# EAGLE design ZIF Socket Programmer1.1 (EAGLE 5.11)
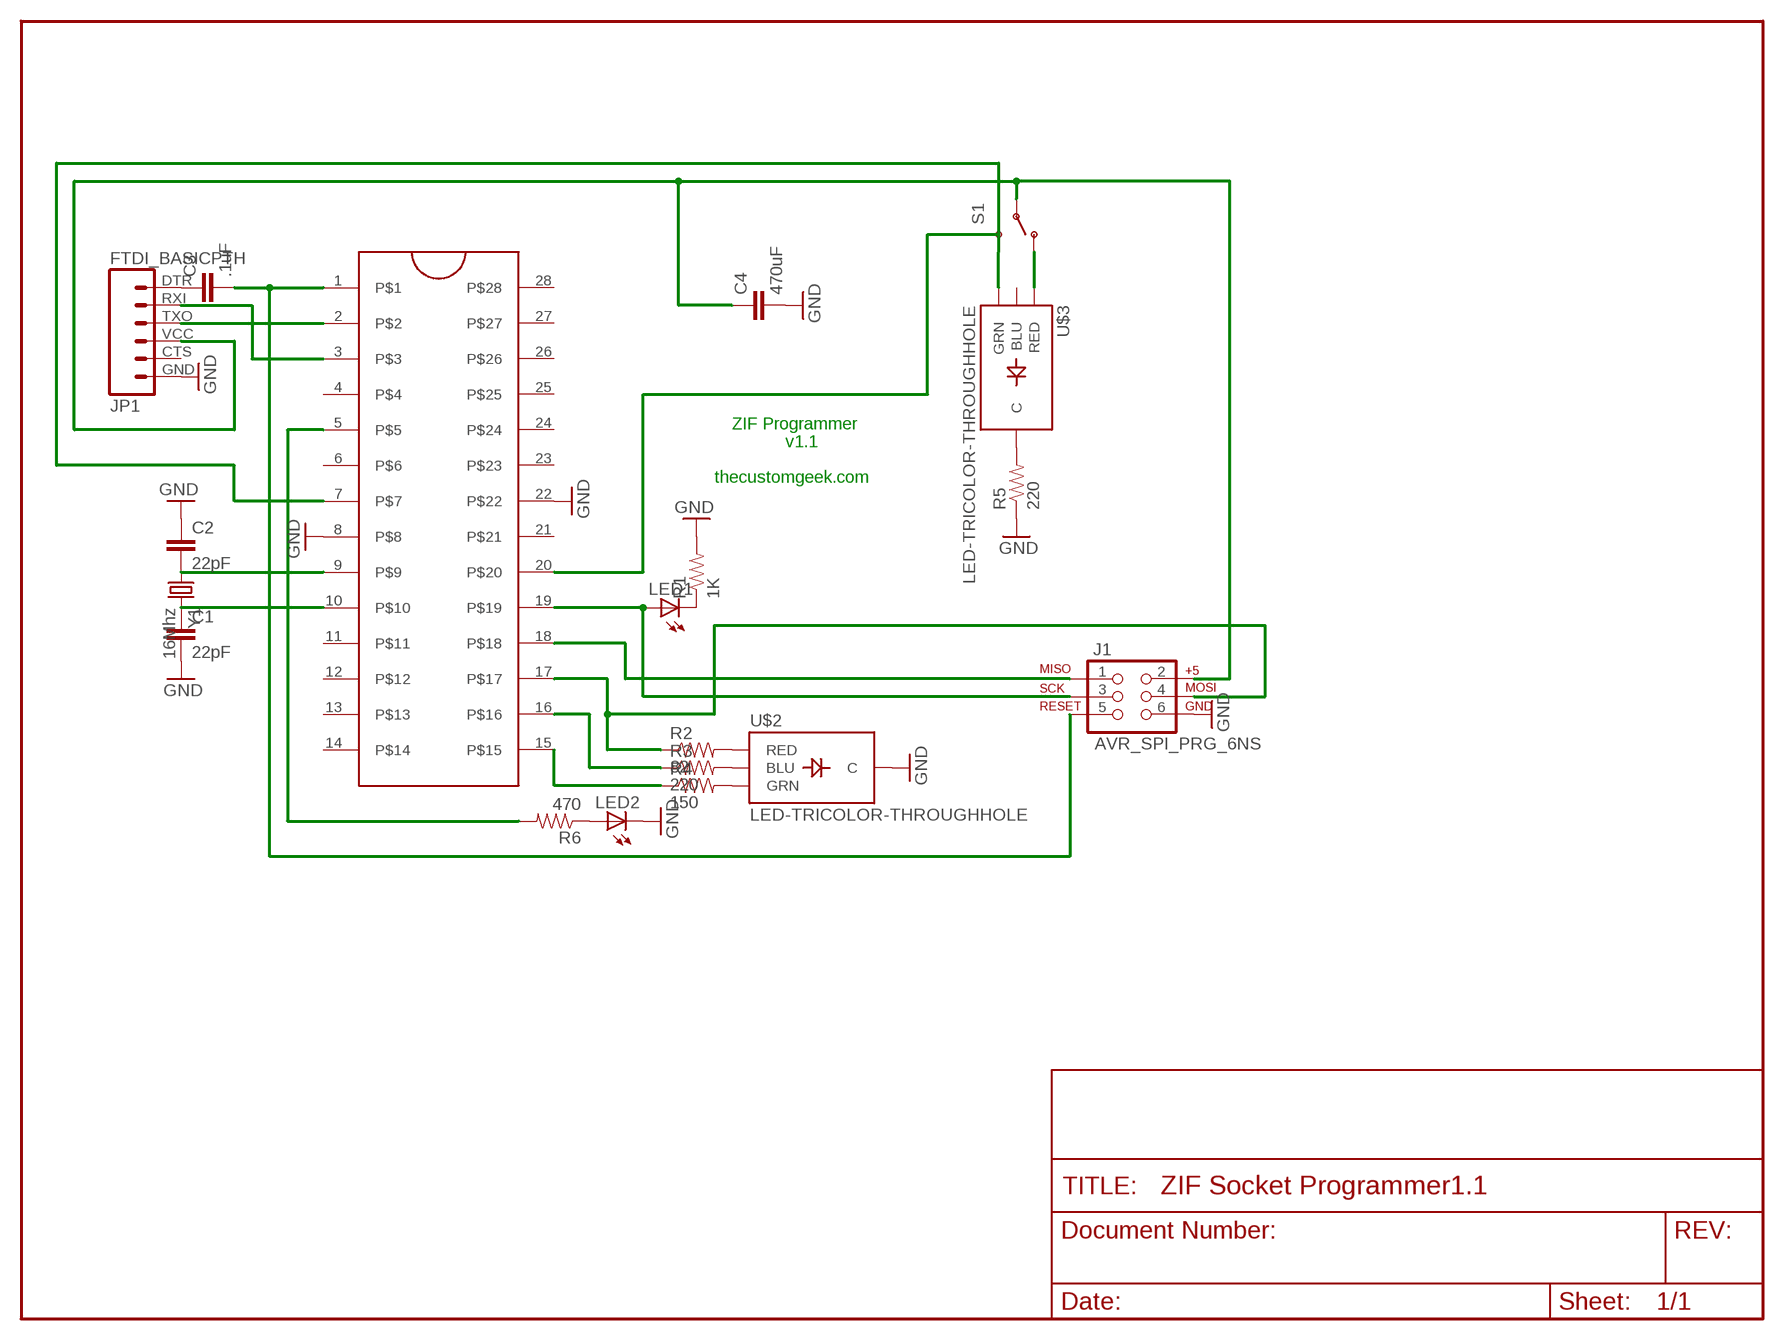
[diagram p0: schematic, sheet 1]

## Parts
C1  22pF  CAPKIT  [CAP-PTH-SMALL-KIT]
C2  22pF  CAPKIT  [CAP-PTH-SMALL-KIT]
C3  .1uF  CAPKIT  [CAP-PTH-SMALL-KIT]
C4  470uF  CAPPTH3  [CAP-PTH-LARGE]
J1  AVR_SPI_PRG_6NS  [2X3-NS]
JP1  FTDI_BASICPTH  [FTDI_BASIC]
LED1  LED3MM  [LED3MM]
LED2  LED3MM  [LED3MM]
R1  1K  RESISTORPTH-1/4W  [AXIAL-0.4]
R2  82  RESISTORPTH-1/4W  [AXIAL-0.4]
R3  220  RESISTORPTH-1/4W  [AXIAL-0.4]
R4  150  RESISTORPTH-1/4W  [AXIAL-0.4]
R5  220  RESISTORPTH-1/4W  [AXIAL-0.4]
R6  470  RESISTORPTH-1/4W  [AXIAL-0.4]
S1  SWITCH-SPSTSMD2  [SWITCH-SPDT-SMD]
U$1  ZIFSOCKET-28-3ZIFFSOCKET-28-3  [DIL28-3-ZIF_SOCKET]
U$2  LED-TRICOLOR-THROUGHHOLE  [LED-TRICOLOR-THROUGHHOLE]
U$3  LED-TRICOLOR-THROUGHHOLE  [LED-TRICOLOR-THROUGHHOLE]
Y1  16Mhz  CRYSTALHC49US  [HC49US]

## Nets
GND: C1.2 C2.1 C4.2 J1.6 JP1.GND LED2.K(C) R1.P$2 R5.P$1 U$1.8 U$1.22 U$2.GND(C)
N$1: J1.1 U$1.18
N$2: J1.3 LED1.A U$1.19
N$3: C3.2 J1.5 U$1.1
N$4: C3.1 JP1.DTR
N$5: LED1.K(C) R1.P$1
N$6: R2.P$2 U$2.RED
N$7: R3.P$2 U$2.BLU
N$8: R4.P$2 U$2.GRN
N$9: R5.P$2 U$3.GND(C)
N$10: LED2.A R6.P$1
N$11: C1.1 U$1.10 Y1.2
N$12: C2.2 U$1.9 Y1.1
N$13: JP1.RXI U$1.3
N$14: JP1.TXO U$1.2
N$15: C4.1 J1.2 JP1.VCC S1.2(P)
N$16: J1.4 R2.P$1 U$1.17
N$17: R3.P$1 U$1.16
N$18: R4.P$1 U$1.15
N$20: S1.1(O) U$3.RED
N$21: S1.3(S) U$1.7 U$1.20 U$3.GRN
N$23: R6.P$2 U$1.5
Unconnected: JP1.CTS U$1.4 U$1.6 U$1.11 U$1.12 U$1.13 U$1.14 U$1.21 U$1.23 U$1.24 U$1.25 U$1.26 U$1.27 U$1.28 U$3.BLU

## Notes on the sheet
- ZIF Programmer
- v1.1
- thecustomgeek.com

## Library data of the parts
C1-C4 = SparkFun:CAP: Capacitor
J1 = SparkFun:AVR_SPI_PRG_6: AVR ISP 6 Pin This is the reduced ISP connector for AVR programming. Common on Arduino. This footprint will take up less PCB space and can be used with a 10-pin to 6-pin adapter such as SKU: BOB-08508
JP1 = SparkFun:FTDI_BASIC: FTDI Basic: 3.3V and 5V
LED1 LED2 = SparkFun:LED: LEDs
R1-R6 = SparkFun:RESISTOR: Resistor
S1 = SparkFun:SWITCH-SPST: SPST Switch Simple slide switch. Spark Fun Electronics SKU : COM-00102
U$1 = SparkFun:ZIFSOCKET-28-3
U$2 U$3 = SparkFun:LED-TRICOLOR-THROUGHHOLE
Y1 = SparkFun:CRYSTAL: Crystals

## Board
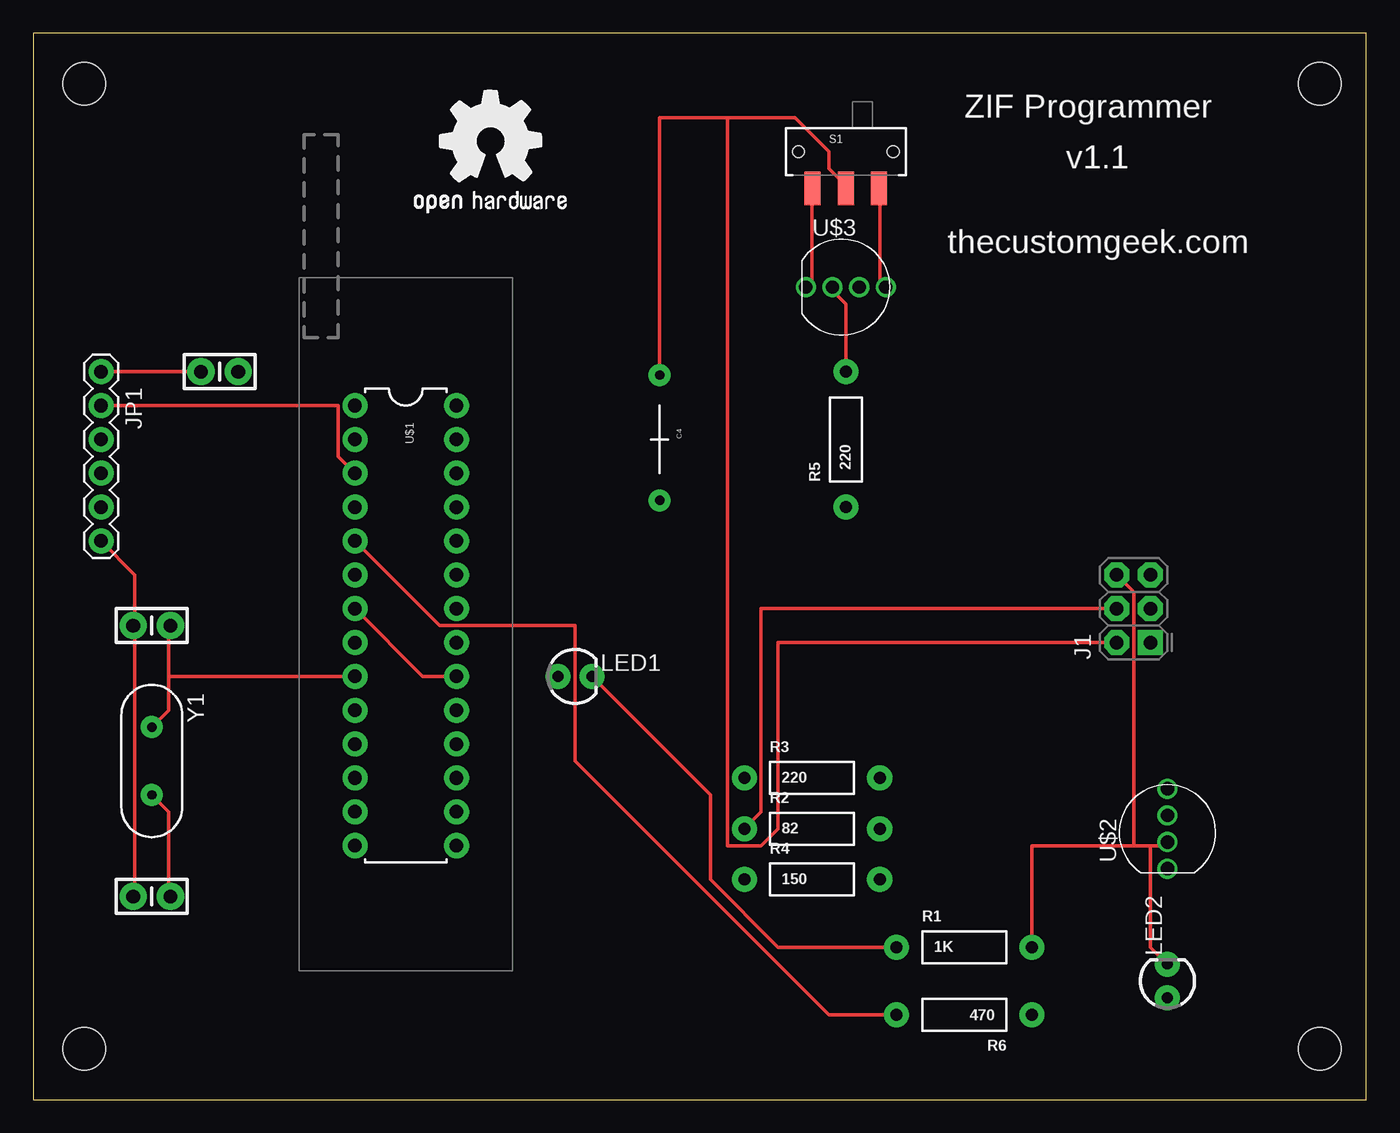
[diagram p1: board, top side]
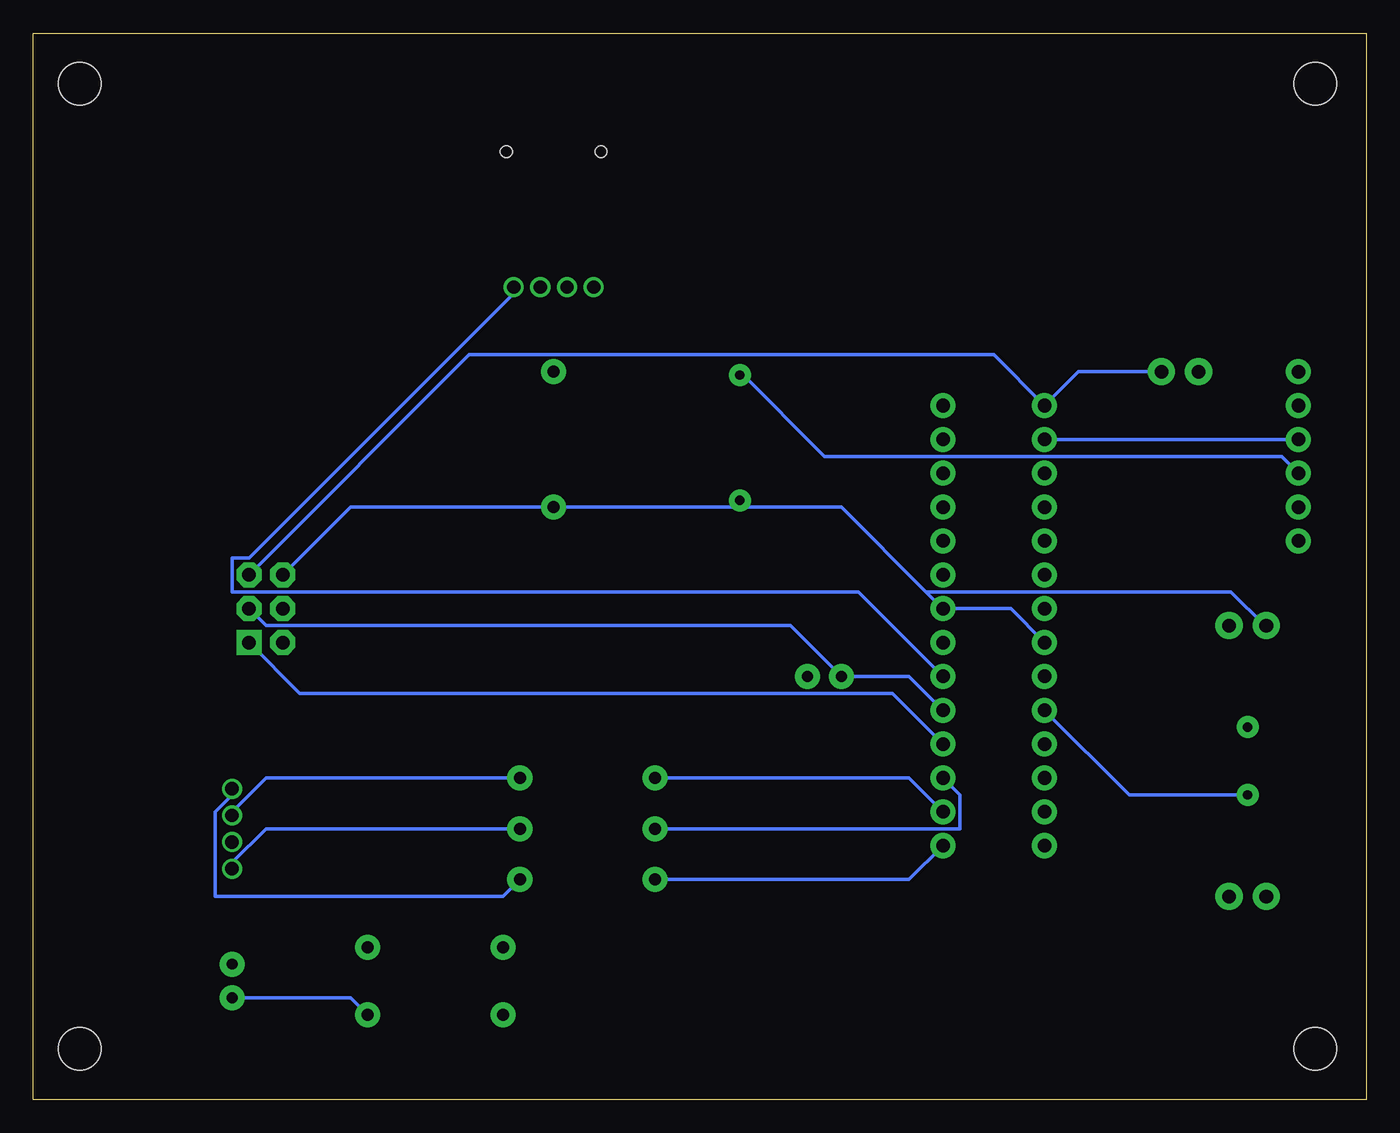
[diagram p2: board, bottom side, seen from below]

Size 100 x 80 mm. Coordinates in mm from the lower left corner, seen from the top.
Outline: 0,0 100,0 100,80 0,80 0,0
Copper layers (1*16): Top 0.035mm / dielectric 1.5mm / Bottom 0.035mm
Design rules "default": minimum track width 10mil, minimum drill 0.6mm, track to track 8mil, track to pad 8mil, pad to pad 8mil, via to via 8mil, smd to smd 8mil, copper to edge 40mil, drill to drill 8mil, minimum pad ring 10mil, minimum via ring 8mil, stop-mask expansion 4mil, vias tented up to drill 0mil, thermal gap 10mil
Holes 3.2 mm at 3.81,76.2 96.52,76.2 96.52,3.81 3.81,3.81

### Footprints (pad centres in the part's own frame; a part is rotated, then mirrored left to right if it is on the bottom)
CAP-PTH-SMALL-KIT = drill 1.016 pad 2.032 round: 1 -1.397,0; 2 1.397,0
CAP-PTH-LARGE = drill 0.7 pad 1.651 round: 1 -4.826,0; 2 4.572,0
2X3-NS = drill 1.016 pad 1.88 square: 1 -2.54,-1.27 | drill 1.016 pad 1.88 octagon: 2 -2.54,1.27; 3 0,-1.27; 4 0,1.27; 5 2.54,-1.27; 6 2.54,1.27
FTDI_BASIC = drill 1.016 pad 1.88 round: CTS 10.16,0; DTR 0,0; GND 12.7,0; RXI 2.54,0; TXO 5.08,0; VCC 7.62,0
LED3MM = drill 0.813 pad 1.88 round: A -1.27,0; K 1.27,0
AXIAL-0.4 = drill 0.9 pad 1.88 round: P$1 -5.08,0; P$2 5.08,0
SWITCH-SPDT-SMD = smd 1.2 x 2.5: 1 -2.5,-2.75; 2 0,-2.75; 3 2.5,-2.75 | hole 0.9: -3.55,0; 3.55,0
DIL28-3-ZIF_SOCKET = drill 1.016 pad 1.88 round: 1 -16.51,-3.81; 2 -13.97,-3.81; 3 -11.43,-3.81; 4 -8.89,-3.81; 5 -6.35,-3.81; 6 -3.81,-3.81; 7 -1.27,-3.81; 8 1.27,-3.81; 9 3.81,-3.81; 10 6.35,-3.81; 11 8.89,-3.81; 12 11.43,-3.81; 13 13.97,-3.81; 14 16.51,-3.81; 15 16.51,3.81; 16 13.97,3.81; 17 11.43,3.81; 18 8.89,3.81; 19 6.35,3.81; 20 3.81,3.81; 21 1.27,3.81; 22 -1.27,3.81; 23 -3.81,3.81; 24 -6.35,3.81; 25 -8.89,3.81; 26 -11.43,3.81; 27 -13.97,3.81; 28 -16.51,3.81
LED-TRICOLOR-THROUGHHOLE = drill 1 round: BLU 1,0; GND -1,0; GRN 3,0; RED -3,0
HC49US = drill 0.7 pad 1.651 round: 1 -2.54,0; 2 2.54,0

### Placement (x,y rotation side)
C1  8.89,15.24 180 top
C2  8.89,35.56 0 top
C3  13.97,54.61 0 top
C4  46.99,49.53 270 top
J1  82.55,36.83 90 top
JP1  5.08,54.61 270 top
LED1  40.64,31.75 0 top
LED2  85.09,8.89 90 top
R1  69.85,11.43 0 top
R2  58.42,20.32 0 top
R3  58.42,24.13 0 top
R4  58.42,16.51 0 top
R5  60.96,49.53 90 top
R6  69.85,6.35 180 top
S1  60.96,71.12 0 top
U$1  27.94,35.56 270 top
U$2  85.09,20.32 90 top
U$3  60.96,60.96 0 top
U$4  [OSHW1]  27.94,64.77 0 top
Y1  8.89,25.4 270 top

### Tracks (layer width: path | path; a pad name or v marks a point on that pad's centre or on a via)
GND
  Top 0.254: 82.55,19.05 74.93,19.05 R1.P$2 | 82.55,19.05 83.82,19.05 | 83.82,19.05 85.09,19.05 U$2.GND | J1.6 82.55,38.1 82.55,19.05 | LED2.K 83.82,11.43 83.82,19.05 | JP1.GND 7.62,39.37 7.62,35.56 | 7.62,35.56 7.62,15.24 C1.2 | 7.62,35.56 C2.1
  Bottom 0.254: U$1.8 26.67,36.83 U$1.22 33.02,38.1 | 46.99,44.45 R5.P$1 76.2,44.45 J1.6 | 33.02,38.1 39.37,44.45 46.99,44.45 | 46.99,44.45 C4.2 | 33.02,38.1 10.16,38.1 7.62,35.56 C2.1
N$1
  Bottom 0.254: U$1.18 35.56,30.48 80.01,30.48 J1.1
N$2
  Bottom 0.254: U$1.19 34.29,31.75 LED1.A 43.18,35.56 82.55,35.56 J1.3
N$3
  Bottom 0.254: 15.24,54.61 C3.2 21.59,54.61 U$1.1 27.94,55.88 67.31,55.88 J1.5
N$4
  Top 0.254: JP1.DTR C3.1 12.7,54.61
N$5
  Top 0.254: LED1.K 50.8,22.86 50.8,16.51 55.88,11.43 R1.P$1
N$6
  Bottom 0.254: R2.P$2 82.55,20.32 85.09,17.78 U$2.RED
N$7
  Bottom 0.254: R3.P$2 82.55,24.13 85.09,21.59 U$2.BLU
N$8
  Bottom 0.254: R4.P$2 64.77,15.24 86.36,15.24 86.36,21.59 85.09,22.86 U$2.GRN
N$9
  Top 0.254: R5.P$2 60.96,59.69 59.69,60.96 U$3.GND
N$10
  Bottom 0.254: R6.P$1 76.2,7.62 LED2.A
N$11
  Top 0.254: Y1.2 10.16,21.59 10.16,15.24 C1.1
  Bottom 0.254: U$1.10 17.78,22.86 Y1.2
N$12
  Top 0.254: Y1.1 10.16,29.21 10.16,31.75 | 10.16,31.75 10.16,35.56 C2.2 | 10.16,31.75 U$1.9
N$13
  Top 0.254: JP1.RXI 22.86,52.07 22.86,48.26 U$1.3
N$14
  Bottom 0.254: JP1.TXO U$1.2
N$15
  Top 0.254: 52.07,73.66 46.99,73.66 C4.1 | 52.07,73.66 57.15,73.66 59.69,71.12 59.69,69.85 60.96,68.58 S1.2 | J1.2 55.88,34.29 55.88,20.32 54.61,19.05 52.07,19.05 52.07,73.66
  Bottom 0.254: JP1.VCC 6.35,48.26 40.64,48.26 46.99,54.61 C4.1
N$16
  Top 0.254: J1.4 54.61,36.83 54.61,21.59 R2.P$1
  Bottom 0.254: U$1.17 30.48,22.86 30.48,20.32 R2.P$1
N$17
  Bottom 0.254: U$1.16 34.29,24.13 R3.P$1
N$18
  Bottom 0.254: U$1.15 34.29,16.51 R4.P$1
N$20
  Top 0.254: S1.1 58.42,67.31 58.42,60.96 U$3.RED
N$21
  Top 0.254: U$1.7 29.21,31.75 U$1.20 | S1.3 63.5,67.31 63.5,60.96 U$3.GRN
  Bottom 0.254: U$1.20 38.1,38.1 85.09,38.1 85.09,40.64 83.82,40.64 63.5,60.96 U$3.GRN
N$23
  Top 0.254: U$1.5 30.48,35.56 40.64,35.56 40.64,25.4 59.69,6.35 R6.P$2

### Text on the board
tPlace: ZIF Programmer | v1.1 | thecustomgeek.com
